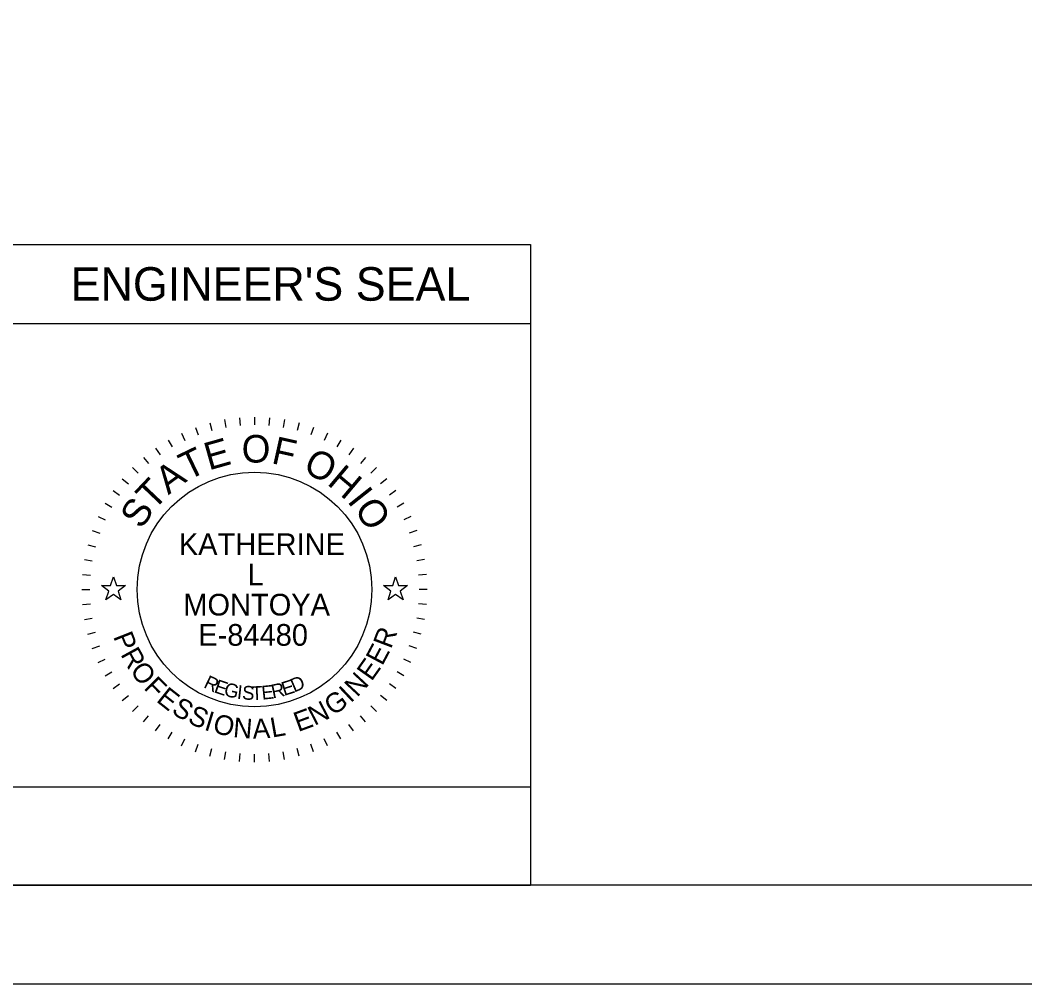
# Model space of a CAD drawing. Extents: x 0 to 34, y 0 to 22.
# Drawn here: x 23.81 to 28.91, y 0 to 4.89 of the extents above; entities that cross this region are included whole.
import ezdxf

# ---------------------------------------------------------------- set-up
doc = ezdxf.new("R2010")
doc.units = 0
for name, color, linetype in [('SH_Border', 7, 'Continuous'), ('SH_Cut_Line', 7, 'Continuous'), ('SH_Data', 7, 'Continuous'), ('SH_Seal', 7, 'Continuous')]:
    doc.layers.add(name, color=color, linetype=linetype)

msp = doc.modelspace()

# ---------------------------------------------------------------- linework, layer by layer
at = {"layer": 'SH_Border'}
msp.add_lwpolyline([(1.5, 21.5), (33.5, 21.5), (33.5, 0.5), (1.5, 0.5)], close=True, dxfattribs=at)
at = {"layer": 'SH_Cut_Line'}
msp.add_lwpolyline([(0, 0), (34, 0), (34, 22), (0, 22)], close=True, dxfattribs=at)
at = {"layer": 'SH_Data'}
for p, q in [((23.6, 3.75), (26.4, 3.75)), ((26.4, 3.75), (26.4, 0.5)), ((23.6, 3.35), (26.4, 3.35)), ((23.6, 0.5), (26.4, 0.5))]:
    msp.add_line(p, q, dxfattribs=at)
msp.add_lwpolyline([(23.6, 0.5), (23.6, 1), (26.4, 1), (26.4, 0.5)], close=True, dxfattribs=at)
at = {"layer": 'SH_Seal'}
for p, q in [((24.8481, 2.8617), (24.855, 2.8223)), ((24.9237, 2.8717), (24.9272, 2.8318)), ((25, 2.875), (25, 2.835)), ((25.0763, 2.8717), (25.0728, 2.8318)), ((25.1519, 2.8617), (25.145, 2.8223)), ((24.7007, 2.8222), (24.7144, 2.7846)), ((24.7735, 2.8452), (24.7839, 2.8065)), ((25.2265, 2.8452), (25.2161, 2.8065)), ((25.2993, 2.8222), (25.2856, 2.7846)), ((24.5625, 2.7578), (24.5825, 2.7231)), ((24.6302, 2.793), (24.6471, 2.7568)), ((25.3698, 2.793), (25.3529, 2.7568)), ((25.4375, 2.7578), (25.4175, 2.7231)), ((24.4981, 2.7168), (24.5211, 2.684)), ((25.5019, 2.7168), (25.4789, 2.684)), ((24.4376, 2.6703), (24.4633, 2.6396)), ((25.5624, 2.6703), (25.5367, 2.6396)), ((24.3813, 2.6187), (24.4096, 2.5904)), ((25.6187, 2.6187), (25.5904, 2.5904)), ((24.3297, 2.5624), (24.3604, 2.5367)), ((25.6703, 2.5624), (25.6396, 2.5367)), ((24.2832, 2.5019), (24.316, 2.4789)), ((25.7168, 2.5019), (25.684, 2.4789)), ((24.2422, 2.4375), (24.2769, 2.4175)), ((25.7578, 2.4375), (25.7231, 2.4175)), ((24.207, 2.3698), (24.2432, 2.3529)), ((25.793, 2.3698), (25.7568, 2.3529)), ((24.1778, 2.2993), (24.2154, 2.2856)), ((25.8222, 2.2993), (25.7846, 2.2856)), ((24.1548, 2.2265), (24.1935, 2.2161)), ((25.8452, 2.2265), (25.8065, 2.2161)), ((24.1383, 2.1519), (24.1777, 2.145)), ((25.8617, 2.1519), (25.8223, 2.145)), ((24.1283, 2.0763), (24.1682, 2.0728)), ((25.8717, 2.0763), (25.8318, 2.0728)), ((24.125, 2), (24.165, 2)), ((25.875, 2), (25.835, 2)), ((24.1283, 1.9237), (24.1682, 1.9272)), ((25.8717, 1.9237), (25.8318, 1.9272)), ((24.1383, 1.8481), (24.1777, 1.855)), ((25.8617, 1.8481), (25.8223, 1.855)), ((24.1548, 1.7735), (24.1935, 1.7839)), ((25.8452, 1.7735), (25.8065, 1.7839)), ((24.1778, 1.7007), (24.2154, 1.7144)), ((25.8222, 1.7007), (25.7846, 1.7144)), ((24.207, 1.6302), (24.2432, 1.6471)), ((25.793, 1.6302), (25.7568, 1.6471)), ((24.2422, 1.5625), (24.2769, 1.5825)), ((25.7578, 1.5625), (25.7231, 1.5825)), ((24.2832, 1.4981), (24.316, 1.5211)), ((25.7168, 1.4981), (25.684, 1.5211)), ((24.3297, 1.4376), (24.3604, 1.4633)), ((25.6703, 1.4376), (25.6396, 1.4633)), ((24.3813, 1.3813), (24.4096, 1.4096)), ((25.6187, 1.3813), (25.5904, 1.4096)), ((24.4376, 1.3297), (24.4633, 1.3604)), ((25.5624, 1.3297), (25.5367, 1.3604)), ((24.4981, 1.2832), (24.5211, 1.316)), ((24.5625, 1.2422), (24.5825, 1.2769)), ((25.4375, 1.2422), (25.4175, 1.2769)), ((25.5019, 1.2832), (25.4789, 1.316)), ((24.6302, 1.207), (24.6471, 1.2432)), ((25.3698, 1.207), (25.3529, 1.2432)), ((24.7007, 1.1778), (24.7144, 1.2154)), ((24.7735, 1.1548), (24.7839, 1.1935)), ((24.8481, 1.1383), (24.855, 1.1777)), ((25.1519, 1.1383), (25.145, 1.1777)), ((25.2265, 1.1548), (25.2161, 1.1935)), ((25.2993, 1.1778), (25.2856, 1.2154)), ((24.9237, 1.1283), (24.9272, 1.1682)), ((25, 1.125), (25, 1.165)), ((25.0763, 1.1283), (25.0728, 1.1682))]:
    msp.add_line(p, q, dxfattribs=at)
for points in [[(24.2236, 2.02), (24.2705, 2.02), (24.285, 2.0645), (24.2995, 2.02), (24.3464, 2.02), (24.3085, 1.9924), (24.323, 1.9478), (24.285, 1.9754), (24.247, 1.9478), (24.2615, 1.9924)], [(25.6536, 2.02), (25.7005, 2.02), (25.715, 2.0645), (25.7295, 2.02), (25.7764, 2.02), (25.7385, 1.9924), (25.753, 1.9478), (25.715, 1.9754), (25.677, 1.9478), (25.6915, 1.9924)]]:
    msp.add_lwpolyline(points, close=True, dxfattribs=at)
msp.add_circle((25, 2), 0.595, dxfattribs=at)

# ---------------------------------------------------------------- texts
at = {"layer": 'SH_Data'}
msp.add_text("ENGINEER'S SEAL", height=0.17, dxfattribs=at).set_placement((24.0676, 3.465))
at = {"layer": 'SH_Seal'}
for s, height, rotation, p in [('E', 0.14, 15.7571, (24.7684, 2.6038)), ('O', 0.14, 359.7812, (24.9347, 2.6443)), ('F', 0.14, 347.4362, (25.0811, 2.6417)), ('T', 0.14, 25.7167, (24.6616, 2.5518)), ('O', 0.14, 332.2586, (25.2398, 2.6015)), ('A', 0.14, 36.4747, (24.5634, 2.4781)), ('H', 0.14, 319.9136, (25.3632, 2.5361)), ('T', 0.14, 46.4344, (24.4883, 2.3964)), ('I', 0.14, 308.367, (25.4665, 2.4483)), ('S', 0.14, 57.1924, (24.4281, 2.3014)), ('O', 0.14, 303.1491, (25.5021, 2.4089)), ('P', 0.1, 291.494, (24.2823, 1.7621)), ('R', 0.1, 69.2322, (25.6919, 1.6954)), ('R', 0.1, 298.7311, (24.319, 1.6717)), ('E', 0.1, 61.9951, (25.6476, 1.6098)), ('E', 0.1, 54.758, (25.5933, 1.5314)), ('O', 0.1, 306.4666, (24.3655, 1.5883)), ('N', 0.1, 47.0224, (25.5202, 1.4508)), ('F', 0.1, 314.7068, (24.4343, 1.4983)), ('R', 0.07, 334.487, (24.7375, 1.5051)), ('E', 0.07, 341.04, (24.7906, 1.4801)), ('E', 0.07, 17.6836, (25.1498, 1.4602)), ('D', 0.07, 23.3052, (25.201, 1.477)), ('E', 0.1, 321.4393, (24.4978, 1.4348)), ('G', 0.07, 347.4752, (24.8414, 1.4618)), ('I', 0.07, 353.7858, (24.9091, 1.4468)), ('S', 0.07, 356.8926, (24.9358, 1.4429)), ('T', 0.07, 3.0061, (24.9857, 1.4387)), ('E', 0.07, 6.0117, (25.0389, 1.4412)), ('R', 0.07, 11.9184, (25.0925, 1.4474)), ('G', 0.1, 35.0469, (25.3981, 1.357)), ('I', 0.1, 43.287, (25.4868, 1.4214)), ('S', 0.1, 328.6764, (24.5743, 1.3752)), ('N', 0.1, 27.3113, (25.3045, 1.3075)), ('S', 0.1, 335.9134, (24.6564, 1.3266)), ('I', 0.1, 343.1505, (24.7406, 1.2897)), ('E', 0.1, 20.0742, (25.2212, 1.277)), ('O', 0.1, 346.8859, (24.7839, 1.2751)), ('N', 0.1, 355.1261, (24.8888, 1.2517)), ('A', 0.1, 2.8617, (24.9923, 1.2437)), ('L', 0.1, 10.0987, (25.0894, 1.249))]:
    msp.add_text(s, height=height, rotation=rotation, dxfattribs=at).set_placement(p)
for s, p in [('KATHERINE', (24.6163, 2.1749)), ('L', (24.9645, 2.0216)), ('MONTOYA', (24.639, 1.8684)), ('E-84480', (24.7149, 1.7151))]:
    msp.add_text(s, height=0.11, dxfattribs=at).set_placement(p)

doc.saveas('drawing.dxf')
